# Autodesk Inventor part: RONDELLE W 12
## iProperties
Created: 2004-11
Part Number: RONDELLE W 12
Document SubType Name: Modeling
Designer: Bruno
Manufacturer: Standard
Standards Organization: Custom
Author: Bruno
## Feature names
1. Base1
